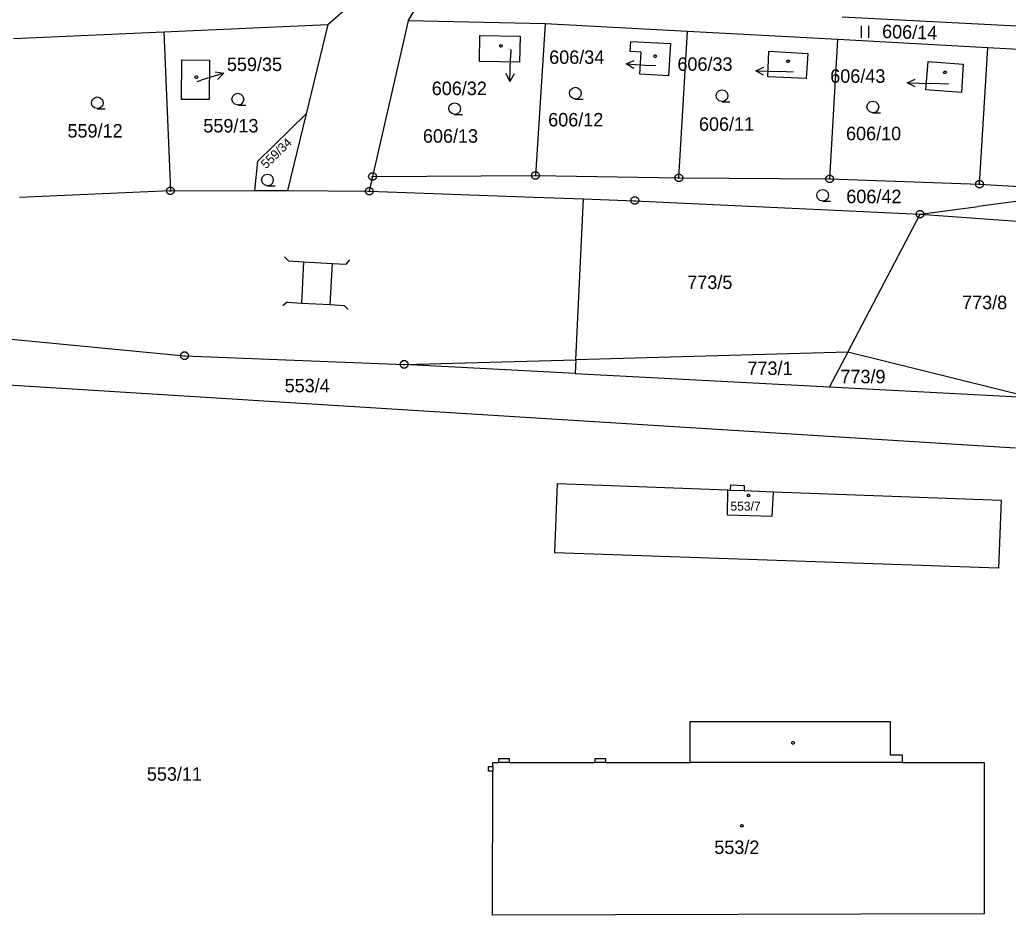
# Model space of a CAD drawing. Extents: x -759699 to -757730, y -1172308 to -1170857.
# Drawn here: x -759051 to -758926.3, y -1171755.4 to -1171642.4 of the extents above; entities that cross this region are included whole.
import ezdxf

# ---------------------------------------------------------------- set-up
doc = ezdxf.new("R2010")
doc.units = 0
for name, color, linetype in [('Vrstva 1', 7, 'Continuous'), ('Vrstva 12', 7, 'Continuous'), ('Vrstva 2', 7, 'Continuous'), ('Vrstva 3', 7, 'Continuous'), ('Vrstva 4', 7, 'Continuous'), ('Vrstva 5', 7, 'Continuous'), ('Vrstva 7', 7, 'Continuous'), ('Vrstva 8', 7, 'Continuous')]:
    doc.layers.add(name, color=color, linetype=linetype)

msp = doc.modelspace()

# ---------------------------------------------------------------- linework, layer by layer
at = {"layer": 'Vrstva 1'}
for p, q in [((-759001.99, -1171642.49), (-758999.19, -1171637.78)), ((-759012.14, -1171642.97), (-759007.87, -1171639.21)), ((-759001.99, -1171642.49), (-759006.48, -1171662.14)), ((-758984.71, -1171642.88), (-759001.99, -1171642.49)), ((-758984.71, -1171642.88), (-758985.93, -1171662.03)), ((-758966.75, -1171643.85), (-758984.71, -1171642.88)), ((-758947.23, -1171641.98), (-758925.22, -1171643.14)), ((-759051.78, -1171644.71), (-759032.82, -1171643.88)), ((-759032.82, -1171643.88), (-759012.14, -1171642.97)), ((-759032.82, -1171643.88), (-759031.99, -1171663.96)), ((-759012.14, -1171642.97), (-759014.86, -1171654.22)), ((-758967.84, -1171662.32), (-758966.75, -1171643.85)), ((-758947.79, -1171644.86), (-758966.75, -1171643.85)), ((-758992.98, -1171647.61), (-758992.93, -1171644.36)), ((-758992.93, -1171644.36), (-758987.87, -1171644.41)), ((-758987.87, -1171644.41), (-758987.93, -1171647.7)), ((-758973.99, -1171646.37), (-758973.88, -1171645.08)), ((-758973.88, -1171645.08), (-758968.91, -1171645.36)), ((-758968.91, -1171645.36), (-758969.14, -1171649.43)), ((-758948.81, -1171662.45), (-758947.79, -1171644.86)), ((-758928.84, -1171645.89), (-758947.79, -1171644.86)), ((-758972.6, -1171646.43), (-758973.99, -1171646.37)), ((-758972.76, -1171649.23), (-758972.6, -1171646.43)), ((-758956.63, -1171649.54), (-758956.5, -1171646.33)), ((-758956.5, -1171646.33), (-758951.58, -1171646.63)), ((-758951.58, -1171646.63), (-758951.77, -1171649.75)), ((-758929.9, -1171663.12), (-758928.84, -1171645.89)), ((-758905.89, -1171647.12), (-758928.84, -1171645.89)), ((-759030.57, -1171652.42), (-759030.56, -1171647.43)), ((-759030.56, -1171647.43), (-759027.06, -1171647.44)), ((-759027.06, -1171647.44), (-759027.08, -1171652.43)), ((-758987.93, -1171647.7), (-758992.98, -1171647.61)), ((-758936.67, -1171651.2), (-758936.4, -1171647.64)), ((-758936.4, -1171647.64), (-758931.98, -1171647.98)), ((-758931.98, -1171647.98), (-758932.19, -1171651.53)), ((-758969.14, -1171649.43), (-758972.76, -1171649.23)), ((-758951.77, -1171649.75), (-758956.63, -1171649.54)), ((-758932.19, -1171651.53), (-758936.67, -1171651.2)), ((-759027.08, -1171652.43), (-759030.57, -1171652.42)), ((-759020.97, -1171660.21), (-759014.86, -1171654.22)), ((-759014.86, -1171654.22), (-759017.2, -1171663.9)), ((-759021.32, -1171663.92), (-759020.97, -1171660.21)), ((-759006.48, -1171662.14), (-759006.9, -1171664)), ((-759006.48, -1171662.14), (-758985.93, -1171662.03)), ((-758985.93, -1171662.03), (-758967.84, -1171662.32)), ((-758967.84, -1171662.32), (-758948.81, -1171662.45)), ((-758948.81, -1171662.45), (-758929.9, -1171663.12)), ((-759031.99, -1171663.96), (-759051.03, -1171664.78)), ((-759031.99, -1171663.96), (-759021.32, -1171663.92)), ((-759021.32, -1171663.92), (-759017.2, -1171663.9)), ((-759017.2, -1171663.9), (-759006.9, -1171664)), ((-759006.9, -1171664), (-758986.1, -1171664.74)), ((-758915.3, -1171663.96), (-758930.07, -1171665.92)), ((-758929.9, -1171663.12), (-758915.3, -1171663.96)), ((-758986.1, -1171664.74), (-758979.89, -1171664.96)), ((-758980.84, -1171685.26), (-758979.89, -1171664.96)), ((-758979.89, -1171664.96), (-758973.39, -1171665.19)), ((-758973.39, -1171665.19), (-758968.02, -1171665.45)), ((-758968.02, -1171665.45), (-758949.04, -1171666.34)), ((-758949.04, -1171666.34), (-758937.4, -1171666.9)), ((-758937.4, -1171666.9), (-758930.07, -1171665.92)), ((-758946.52, -1171684.31), (-758937.4, -1171666.9)), ((-758937.4, -1171666.9), (-758912.26, -1171668.73)), ((-759057.29, -1171682.16), (-759030.21, -1171684.76)), ((-759030.21, -1171684.76), (-759002.49, -1171685.86)), ((-759002.49, -1171685.86), (-758980.84, -1171685.26)), ((-758946.52, -1171684.31), (-758980.84, -1171685.26)), ((-758946.52, -1171684.31), (-758948.82, -1171688.7)), ((-758923.44, -1171690.05), (-758946.52, -1171684.31)), ((-758980.92, -1171687), (-759002.49, -1171685.86)), ((-759070.89, -1171687.29), (-758925.35, -1171696.39)), ((-758980.92, -1171687), (-758948.82, -1171688.7)), ((-758948.82, -1171688.7), (-758923.44, -1171690.05)), ((-758983.49, -1171709.64), (-758983.16, -1171700.89)), ((-758983.16, -1171700.89), (-758961.71, -1171701.7)), ((-758961.31, -1171701.71), (-758961.28, -1171701.05)), ((-758961.28, -1171701.05), (-758959.58, -1171701.12)), ((-758959.58, -1171701.12), (-758959.61, -1171701.78)), ((-758961.71, -1171701.7), (-758961.31, -1171701.71)), ((-758959.61, -1171701.78), (-758955.91, -1171701.92)), ((-758955.91, -1171701.92), (-758927.16, -1171703)), ((-758927.16, -1171703), (-758927.53, -1171711.59)), ((-758927.53, -1171711.59), (-758983.49, -1171709.64)), ((-758966.4, -1171736.1), (-758966.4, -1171730.91)), ((-758966.4, -1171730.91), (-758941.2, -1171730.91)), ((-758941.2, -1171730.91), (-758941.2, -1171735.12)), ((-758941.2, -1171735.12), (-758939.67, -1171735.12)), ((-758939.67, -1171735.12), (-758939.67, -1171736.1)), ((-758991.33, -1171736.62), (-758991.33, -1171736.1)), ((-758991.33, -1171736.1), (-758990.57, -1171736.1)), ((-758990.57, -1171736.1), (-758990.57, -1171735.6)), ((-758990.57, -1171735.6), (-758989.27, -1171735.6)), ((-758989.27, -1171735.6), (-758989.27, -1171736.1)), ((-758989.27, -1171736.1), (-758978.4, -1171736.1)), ((-758978.4, -1171736.1), (-758978.4, -1171735.6)), ((-758978.4, -1171735.6), (-758977.08, -1171735.6)), ((-758977.08, -1171735.6), (-758977.08, -1171736.1)), ((-758977.08, -1171736.1), (-758966.4, -1171736.1)), ((-758939.67, -1171736.1), (-758929.33, -1171736.1)), ((-758929.33, -1171736.1), (-758929.31, -1171755.2)), ((-758991.85, -1171737.21), (-758991.85, -1171736.62)), ((-758991.85, -1171736.62), (-758991.33, -1171736.62)), ((-758991.33, -1171737.21), (-758991.85, -1171737.21)), ((-758991.36, -1171755.38), (-758991.33, -1171737.21)), ((-758929.31, -1171755.2), (-758991.36, -1171755.38))]:
    msp.add_line(p, q, dxfattribs=at)
at = {"layer": 'Vrstva 12'}
for p, q in [((-758992.98, -1171647.61), (-758992.93, -1171644.36)), ((-758992.93, -1171644.36), (-758987.87, -1171644.41)), ((-758987.87, -1171644.41), (-758987.93, -1171647.7)), ((-758973.99, -1171646.37), (-758973.88, -1171645.08)), ((-758973.88, -1171645.08), (-758968.91, -1171645.36)), ((-758968.91, -1171645.36), (-758969.14, -1171649.43)), ((-758972.6, -1171646.43), (-758973.99, -1171646.37)), ((-758972.76, -1171649.23), (-758972.6, -1171646.43)), ((-758956.63, -1171649.54), (-758956.5, -1171646.33)), ((-758956.5, -1171646.33), (-758951.58, -1171646.63)), ((-758951.58, -1171646.63), (-758951.77, -1171649.75)), ((-759030.57, -1171652.42), (-759030.56, -1171647.43)), ((-759030.56, -1171647.43), (-759027.06, -1171647.44)), ((-759027.06, -1171647.44), (-759027.08, -1171652.43)), ((-758987.93, -1171647.7), (-758992.98, -1171647.61)), ((-758936.67, -1171651.2), (-758936.4, -1171647.64)), ((-758936.4, -1171647.64), (-758931.98, -1171647.98)), ((-758931.98, -1171647.98), (-758932.19, -1171651.53)), ((-758969.14, -1171649.43), (-758972.76, -1171649.23)), ((-758951.77, -1171649.75), (-758956.63, -1171649.54)), ((-758932.19, -1171651.53), (-758936.67, -1171651.2)), ((-759027.08, -1171652.43), (-759030.57, -1171652.42)), ((-758961.71, -1171701.7), (-758961.75, -1171704.83)), ((-758961.71, -1171701.7), (-758961.31, -1171701.71)), ((-758961.31, -1171701.71), (-758959.61, -1171701.78)), ((-758959.61, -1171701.78), (-758955.91, -1171701.92)), ((-758956.05, -1171705.03), (-758955.91, -1171701.92)), ((-758961.75, -1171704.83), (-758956.05, -1171705.03)), ((-758991.33, -1171736.62), (-758991.33, -1171736.1)), ((-758991.33, -1171736.1), (-758990.57, -1171736.1)), ((-758989.27, -1171736.1), (-758990.57, -1171736.1)), ((-758989.27, -1171736.1), (-758978.4, -1171736.1)), ((-758977.08, -1171736.1), (-758978.4, -1171736.1)), ((-758977.08, -1171736.1), (-758966.4, -1171736.1)), ((-758939.67, -1171736.1), (-758966.4, -1171736.1)), ((-758939.67, -1171736.1), (-758929.33, -1171736.1)), ((-758929.33, -1171736.1), (-758929.31, -1171755.2)), ((-758991.36, -1171755.38), (-758991.33, -1171737.21)), ((-758991.33, -1171736.62), (-758991.33, -1171737.21)), ((-758929.31, -1171755.2), (-758991.36, -1171755.38))]:
    msp.add_line(p, q, dxfattribs=at)
at = {"layer": 'Vrstva 3'}
for p, q in [((-758944.86, -1171643.14), (-758944.86, -1171644.64)), ((-758943.86, -1171644.64), (-758943.86, -1171643.14))]:
    msp.add_line(p, q, dxfattribs=at)
for points in [[(-759023.47, -1171653.11), (-759023.85, -1171653.01), (-759024.12, -1171652.74), (-759024.22, -1171652.37), (-759024.12, -1171652), (-759023.85, -1171651.73), (-759023.48, -1171651.63), (-759023.11, -1171651.73), (-759022.84, -1171652), (-759022.74, -1171652.38), (-759022.84, -1171652.76), (-759023.11, -1171653.03), (-759023.49, -1171653.13), (-759022.49, -1171653.13)], [(-758980.89, -1171652.36), (-758981.27, -1171652.26), (-758981.54, -1171651.99), (-758981.64, -1171651.62), (-758981.54, -1171651.25), (-758981.27, -1171650.98), (-758980.9, -1171650.88), (-758980.53, -1171650.98), (-758980.26, -1171651.25), (-758980.16, -1171651.63), (-758980.26, -1171652.01), (-758980.53, -1171652.28), (-758980.91, -1171652.38), (-758979.91, -1171652.38)], [(-758962.39, -1171652.68), (-758962.77, -1171652.58), (-758963.04, -1171652.31), (-758963.14, -1171651.94), (-758963.04, -1171651.57), (-758962.77, -1171651.3), (-758962.4, -1171651.2), (-758962.03, -1171651.3), (-758961.76, -1171651.57), (-758961.66, -1171651.95), (-758961.76, -1171652.33), (-758962.03, -1171652.6), (-758962.41, -1171652.7), (-758961.41, -1171652.7)], [(-759041.2, -1171653.57), (-759041.58, -1171653.47), (-759041.85, -1171653.2), (-759041.95, -1171652.83), (-759041.85, -1171652.46), (-759041.58, -1171652.19), (-759041.21, -1171652.09), (-759040.84, -1171652.19), (-759040.57, -1171652.46), (-759040.47, -1171652.84), (-759040.57, -1171653.22), (-759040.84, -1171653.49), (-759041.22, -1171653.59), (-759040.22, -1171653.59)], [(-758996.11, -1171654.3), (-758996.49, -1171654.2), (-758996.76, -1171653.93), (-758996.86, -1171653.56), (-758996.76, -1171653.19), (-758996.49, -1171652.92), (-758996.12, -1171652.82), (-758995.75, -1171652.92), (-758995.48, -1171653.19), (-758995.38, -1171653.57), (-758995.48, -1171653.95), (-758995.75, -1171654.22), (-758996.13, -1171654.32), (-758995.13, -1171654.32)], [(-758943.36, -1171654.09), (-758943.74, -1171653.99), (-758944.01, -1171653.72), (-758944.11, -1171653.35), (-758944.01, -1171652.98), (-758943.74, -1171652.71), (-758943.37, -1171652.61), (-758943, -1171652.71), (-758942.73, -1171652.98), (-758942.63, -1171653.36), (-758942.73, -1171653.74), (-758943, -1171654.01), (-758943.38, -1171654.11), (-758942.38, -1171654.11)], [(-759019.74, -1171663.31), (-759020.12, -1171663.21), (-759020.39, -1171662.94), (-759020.49, -1171662.57), (-759020.39, -1171662.2), (-759020.12, -1171661.93), (-759019.75, -1171661.83), (-759019.38, -1171661.93), (-759019.11, -1171662.2), (-759019.01, -1171662.58), (-759019.11, -1171662.96), (-759019.38, -1171663.23), (-759019.76, -1171663.33), (-759018.76, -1171663.33)], [(-758949.68, -1171665.25), (-758950.06, -1171665.15), (-758950.33, -1171664.88), (-758950.43, -1171664.51), (-758950.33, -1171664.14), (-758950.06, -1171663.87), (-758949.69, -1171663.77), (-758949.32, -1171663.87), (-758949.05, -1171664.14), (-758948.95, -1171664.52), (-758949.05, -1171664.9), (-758949.32, -1171665.17), (-758949.7, -1171665.27), (-758948.7, -1171665.27)]]:
    msp.add_lwpolyline(points, dxfattribs=at)
at = {"layer": 'Vrstva 4'}
for p, q in [((-759017.09, -1171672.79), (-759017.584, -1171672.284)), ((-759017.09, -1171672.79), (-759015.21, -1171672.9)), ((-759009.81, -1171673.22), (-759009.369, -1171672.668)), ((-759015.21, -1171672.9), (-759015.45, -1171678.12)), ((-759015.21, -1171672.9), (-759011.56, -1171673.12)), ((-759011.83, -1171678.31), (-759011.56, -1171673.12)), ((-759011.56, -1171673.12), (-759009.81, -1171673.22)), ((-759017.24, -1171678.02), (-759017.802, -1171678.449)), ((-759017.24, -1171678.02), (-759015.45, -1171678.12)), ((-759015.45, -1171678.12), (-759011.83, -1171678.31)), ((-759011.83, -1171678.31), (-759010.05, -1171678.41)), ((-759010.05, -1171678.41), (-759009.557, -1171678.917)), ((-758980.84, -1171685.26), (-758980.92, -1171687)), ((-758961.71, -1171701.7), (-758961.75, -1171704.83)), ((-758961.31, -1171701.71), (-758959.61, -1171701.78)), ((-758956.05, -1171705.03), (-758955.91, -1171701.92)), ((-758961.75, -1171704.83), (-758956.05, -1171705.03)), ((-758989.27, -1171736.1), (-758990.57, -1171736.1)), ((-758977.08, -1171736.1), (-758978.4, -1171736.1)), ((-758939.67, -1171736.1), (-758966.4, -1171736.1)), ((-758991.33, -1171736.62), (-758991.33, -1171737.21))]:
    msp.add_line(p, q, dxfattribs=at)
at = {"layer": 'Vrstva 5'}
for points in [[(-758990.21, -1171645.5), (-758990.12, -1171645.65), (-758990.21, -1171645.8), (-758990.39, -1171645.8), (-758990.48, -1171645.65), (-758990.39, -1171645.5)], [(-758970.74, -1171646.8), (-758970.65, -1171646.95), (-758970.74, -1171647.1), (-758970.92, -1171647.1), (-758971.01, -1171646.95), (-758970.92, -1171646.8)], [(-758953.97, -1171647.45), (-758953.88, -1171647.6), (-758953.97, -1171647.75), (-758954.15, -1171647.75), (-758954.24, -1171647.6), (-758954.15, -1171647.45)], [(-758934.18, -1171648.85), (-758934.09, -1171649), (-758934.18, -1171649.15), (-758934.36, -1171649.15), (-758934.45, -1171649), (-758934.36, -1171648.85)], [(-759028.63, -1171649.45), (-759028.54, -1171649.6), (-759028.63, -1171649.75), (-759028.81, -1171649.75), (-759028.9, -1171649.6), (-759028.81, -1171649.45)], [(-758958.97, -1171702.24), (-758958.88, -1171702.39), (-758958.97, -1171702.54), (-758959.15, -1171702.54), (-758959.24, -1171702.39), (-758959.15, -1171702.24)], [(-758953.35, -1171733.47), (-758953.26, -1171733.62), (-758953.35, -1171733.77), (-758953.53, -1171733.77), (-758953.62, -1171733.62), (-758953.53, -1171733.47)], [(-758959.8, -1171743.94), (-758959.71, -1171744.09), (-758959.8, -1171744.24), (-758959.98, -1171744.24), (-758960.07, -1171744.09), (-758959.98, -1171743.94)]]:
    msp.add_lwpolyline(points, close=True, dxfattribs=at)
at = {"layer": 'Vrstva 7'}
for p, q in [((-758989.05, -1171646.1), (-758989.08, -1171647.16)), ((-758989.16, -1171650.159), (-758989.08, -1171647.16)), ((-759025.251, -1171649.113), (-759028.12, -1171649.99)), ((-758974.493, -1171647.921), (-758971.5, -1171648.13)), ((-758970.79, -1171648.18), (-758971.5, -1171648.13)), ((-758958.138, -1171648.799), (-758955.14, -1171648.9)), ((-758953.4, -1171648.96), (-758955.14, -1171648.9)), ((-759028.62, -1171650.14), (-759028.12, -1171649.99)), ((-758939.029, -1171650.308), (-758936.03, -1171650.4)), ((-758933.82, -1171650.47), (-758936.03, -1171650.4))]:
    msp.add_line(p, q, dxfattribs=at)
for points in [[(-758973.53, -1171648.489), (-758974.493, -1171647.921), (-758973.46, -1171647.492)], [(-759026.353, -1171648.927), (-759025.251, -1171649.113), (-759026.061, -1171649.884)], [(-758988.633, -1171649.173), (-758989.16, -1171650.159), (-758989.633, -1171649.146)], [(-758957.156, -1171649.332), (-758958.138, -1171648.799), (-758957.122, -1171648.333)], [(-758938.044, -1171650.838), (-758939.029, -1171650.308), (-758938.014, -1171649.839)]]:
    msp.add_lwpolyline(points, dxfattribs=at)
at = {"layer": 'Vrstva 8'}
for p, q in [((-759006.6, -1171662.14), (-759006.36, -1171662.14)), ((-758986.05, -1171662.03), (-758985.81, -1171662.03)), ((-758967.96, -1171662.32), (-758967.72, -1171662.32)), ((-758948.93, -1171662.45), (-758948.69, -1171662.45)), ((-759032.11, -1171663.96), (-759031.87, -1171663.96)), ((-759007.02, -1171664), (-759006.78, -1171664)), ((-758930.02, -1171663.12), (-758929.78, -1171663.12)), ((-758973.51, -1171665.19), (-758973.27, -1171665.19)), ((-758937.52, -1171666.9), (-758937.28, -1171666.9)), ((-759030.33, -1171684.76), (-759030.09, -1171684.76)), ((-759002.61, -1171685.86), (-759002.37, -1171685.86))]:
    msp.add_line(p, q, dxfattribs=at)
for points in [[(-758985.78, -1171661.55), (-758985.53, -1171661.73), (-758985.43, -1171662.02), (-758985.53, -1171662.31), (-758985.78, -1171662.49), (-758986.09, -1171662.49), (-758986.34, -1171662.31), (-758986.44, -1171662.02), (-758986.34, -1171661.73), (-758986.09, -1171661.55)], [(-759006.33, -1171661.66), (-759006.08, -1171661.84), (-759005.98, -1171662.13), (-759006.08, -1171662.42), (-759006.33, -1171662.6), (-759006.64, -1171662.6), (-759006.89, -1171662.42), (-759006.99, -1171662.13), (-759006.89, -1171661.84), (-759006.64, -1171661.66)], [(-758967.69, -1171661.84), (-758967.44, -1171662.02), (-758967.34, -1171662.31), (-758967.44, -1171662.6), (-758967.69, -1171662.78), (-758968, -1171662.78), (-758968.25, -1171662.6), (-758968.35, -1171662.31), (-758968.25, -1171662.02), (-758968, -1171661.84)], [(-758948.66, -1171661.97), (-758948.41, -1171662.15), (-758948.31, -1171662.44), (-758948.41, -1171662.73), (-758948.66, -1171662.91), (-758948.97, -1171662.91), (-758949.22, -1171662.73), (-758949.32, -1171662.44), (-758949.22, -1171662.15), (-758948.97, -1171661.97)], [(-758929.75, -1171662.64), (-758929.5, -1171662.82), (-758929.4, -1171663.11), (-758929.5, -1171663.4), (-758929.75, -1171663.58), (-758930.06, -1171663.58), (-758930.31, -1171663.4), (-758930.41, -1171663.11), (-758930.31, -1171662.82), (-758930.06, -1171662.64)], [(-759031.84, -1171663.48), (-759031.59, -1171663.66), (-759031.49, -1171663.95), (-759031.59, -1171664.24), (-759031.84, -1171664.42), (-759032.15, -1171664.42), (-759032.4, -1171664.24), (-759032.5, -1171663.95), (-759032.4, -1171663.66), (-759032.15, -1171663.48)], [(-759006.75, -1171663.52), (-759006.5, -1171663.7), (-759006.4, -1171663.99), (-759006.5, -1171664.28), (-759006.75, -1171664.46), (-759007.06, -1171664.46), (-759007.31, -1171664.28), (-759007.41, -1171663.99), (-759007.31, -1171663.7), (-759007.06, -1171663.52)], [(-758973.24, -1171664.71), (-758972.99, -1171664.89), (-758972.89, -1171665.18), (-758972.99, -1171665.47), (-758973.24, -1171665.65), (-758973.55, -1171665.65), (-758973.8, -1171665.47), (-758973.9, -1171665.18), (-758973.8, -1171664.89), (-758973.55, -1171664.71)], [(-758937.25, -1171666.42), (-758937, -1171666.6), (-758936.9, -1171666.89), (-758937, -1171667.18), (-758937.25, -1171667.36), (-758937.56, -1171667.36), (-758937.81, -1171667.18), (-758937.91, -1171666.89), (-758937.81, -1171666.6), (-758937.56, -1171666.42)], [(-759030.06, -1171684.28), (-759029.81, -1171684.46), (-759029.71, -1171684.75), (-759029.81, -1171685.04), (-759030.06, -1171685.22), (-759030.37, -1171685.22), (-759030.62, -1171685.04), (-759030.72, -1171684.75), (-759030.62, -1171684.46), (-759030.37, -1171684.28)], [(-759002.34, -1171685.38), (-759002.09, -1171685.56), (-759001.99, -1171685.85), (-759002.09, -1171686.14), (-759002.34, -1171686.32), (-759002.65, -1171686.32), (-759002.9, -1171686.14), (-759003, -1171685.85), (-759002.9, -1171685.56), (-759002.65, -1171685.38)]]:
    msp.add_lwpolyline(points, close=True, dxfattribs=at)

# ---------------------------------------------------------------- texts
at = {"layer": 'Vrstva 2'}
for s, height, rotation, p in [('606/14', 1.7, 358.27051, (-758942.219, -1171644.655)), ('559/34', 1.14, 44.11775, (-759019.912, -1171661.229))]:
    msp.add_text(s, height=height, rotation=rotation, dxfattribs=at).set_placement(p)
for s, height, p in [('606/32', 0.1, (-758989.304, -1171646.1)), ('606/34', 0.1, (-758971.039, -1171648.18)), ('606/33', 0.1, (-758953.654, -1171648.96)), ('559/35', 0.1, (-759028.606, -1171650.14)), ('606/43', 0.1, (-758934.069, -1171650.47)), ('606/12', 1.7, (-758984.325, -1171655.82)), ('559/13', 1.7, (-759027.835, -1171656.58)), ('606/11', 1.7, (-758965.303, -1171656.37)), ('559/12', 1.7, (-759044.972, -1171657.22)), ('606/13', 1.7, (-759000.128, -1171657.87)), ('606/10', 1.7, (-758946.748, -1171657.56)), ('606/42', 1.7, (-758946.713, -1171665.51)), ('773/5', 1.7, (-758966.777, -1171676.34)), ('773/8', 1.7, (-758932.11, -1171678.88)), ('773/1', 1.7, (-758959.192, -1171687.19)), ('773/9', 1.7, (-758947.46, -1171688.24)), ('553/4', 1.7, (-759017.574, -1171689.38)), ('553/7', 1.14, (-758961.337, -1171704.32)), ('553/11', 1.7, (-759034.957, -1171738.4)), ('553/2', 1.7, (-758963.368, -1171747.65))]:
    msp.add_text(s, height=height, dxfattribs=at).set_placement(p)
at = {"layer": 'Vrstva 7'}
for s, p in [('606/34', (-758984.2, -1171647.92)), ('559/35', (-759024.86, -1171648.83)), ('606/33', (-758968.025, -1171648.8)), ('606/43', (-758948.74, -1171650.31)), ('606/32', (-758999.018, -1171651.86))]:
    msp.add_text(s, height=1.7, dxfattribs=at).set_placement(p)

doc.saveas('drawing.dxf')
